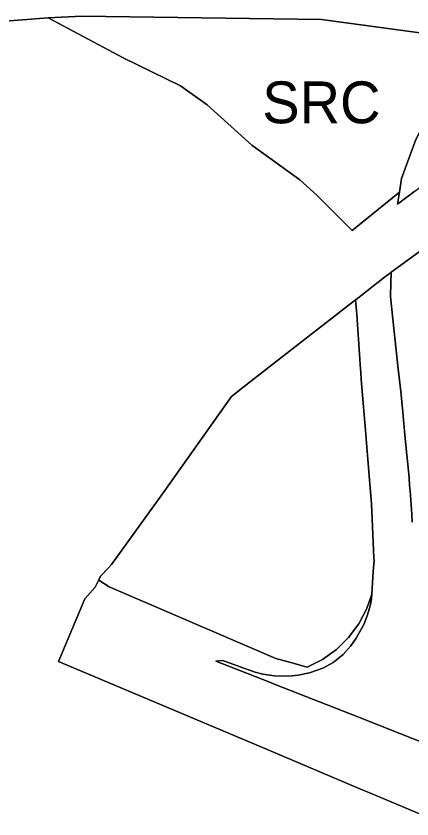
# Model space of a CAD drawing. Extents: x 598968 to 613553, y 4409678 to 4430833.
# Drawn here: x 607149.2 to 607262.7, y 4416952.5 to 4417182.7 of the extents above; entities that cross this region are included whole.
import ezdxf

# ---------------------------------------------------------------- set-up
doc = ezdxf.new("R2010")
doc.units = 0
for name, color, linetype in [('1', 7, 'Continuous'), ('Sòl Rústic Comú', 7, 'Continuous'), ('Sòl Rústic Protegit', 7, 'Continuous')]:
    doc.layers.add(name, color=color, linetype=linetype)

msp = doc.modelspace()

# ---------------------------------------------------------------- linework, layer by layer
at = {"layer": '1'}
for points in [[(607274.8714, 4417122.4396), (607256.7531, 4417109.2766), (607256.6325, 4417106.0969), (607256.4872, 4417102.2661), (607257.1786, 4417095.7896), (607258.7038, 4417081.5028), (607259.4393, 4417074.9859), (607260.0228, 4417069.1469), (607260.0232, 4417069.1429), (607260.6743, 4417062.6279), (607260.9549, 4417059.6622), (607261.7414, 4417051.35), (607261.8422, 4417050.2843), (607261.9968, 4417048.0768), (607262.1401, 4417046.5474), (607262.6256, 4417039.8621), (607262.7304, 4417037.6034)], [(607262.7304, 4417037.6034), (607262.6256, 4417039.8621), (607262.1401, 4417046.5474), (607261.9968, 4417048.0768), (607261.8422, 4417050.2843), (607261.7414, 4417051.35), (607260.9549, 4417059.6622), (607260.6743, 4417062.6279), (607260.0232, 4417069.1429), (607260.0228, 4417069.1469), (607259.4393, 4417074.9859), (607258.7038, 4417081.5028), (607257.1786, 4417095.7896), (607256.4872, 4417102.2661), (607256.6325, 4417106.0969), (607256.7531, 4417109.2766), (607256.7239, 4417109.2554), (607256.4972, 4417109.0907), (607254.4609, 4417107.5042), (607254.369, 4417107.4327), (607246.6902, 4417101.4506), (607246.5298, 4417101.3256), (607246.8279, 4417097.1465), (607247.7412, 4417084.3437), (607247.847, 4417082.7605), (607248.0066, 4417080.3707), (607248.1589, 4417078.4891), (607248.163, 4417078.4378), (607249.5244, 4417061.6174), (607249.5394, 4417061.4308), (607250.1994, 4417053.2371), (607251.042, 4417042.7774), (607251.7855, 4417027.3151), (607251.8196, 4417026.6064), (607251.594, 4417023.4169), (607251.1364, 4417016.9491), (607251.0446, 4417015.6515), (607250.7897, 4417013.8765), (607249.8187, 4417010.6774), (607248.8658, 4417008.2616), (607246.6477, 4417004.3067), (607245.1448, 4417002.0815), (607242.9298, 4416999.6615), (607240.0698, 4416997.3065), (607237.1107, 4416995.6767), (607233.2899, 4416994.3464), (607230.04, 4416993.6864), (607228.3118, 4416993.5449), (607226.74, 4416993.4163), (607223.2148, 4416993.4764), (607219.8901, 4416993.9362), (607217.783, 4416994.55), (607213.4401, 4416996.076), (607208.5102, 4416997.9059), (607207.2773, 4416997.7617), (607206.462, 4416997.6663), (607221.2228, 4416991.9327), (607223.4907, 4416991.0402), (607247.149, 4416981.7304), (607259.2318, 4416976.9757), (607266.9733, 4416973.9293)], [(607266.9733, 4416973.9293), (607259.2318, 4416976.9757), (607247.149, 4416981.7304), (607223.4907, 4416991.0402), (607221.2228, 4416991.9327), (607206.462, 4416997.6663), (607207.2773, 4416997.7617), (607208.5102, 4416997.9059), (607213.4401, 4416996.076), (607217.783, 4416994.55), (607219.8901, 4416993.9362), (607223.2148, 4416993.4764), (607226.74, 4416993.4163), (607228.3118, 4416993.5449), (607230.04, 4416993.6864), (607233.2899, 4416994.3464), (607237.1107, 4416995.6767), (607240.0698, 4416997.3065), (607242.9298, 4416999.6615), (607245.1448, 4417002.0815), (607246.6477, 4417004.3067), (607248.8658, 4417008.2616), (607249.8187, 4417010.6774), (607250.7897, 4417013.8765), (607251.0446, 4417015.6515), (607251.1364, 4417016.9491), (607249.7129, 4417012.7857), (607247.4325, 4417008.4436), (607244.5127, 4417004.5029), (607241.0225, 4417001.0572), (607237.0448, 4416998.1881), (607232.6737, 4416995.9635), (607227.6081, 4416997.3796), (607223.6633, 4416998.4825), (607175.9173, 4417019.0222), (607172.9624, 4417020.9478), (607172.8855, 4417020.998), (607171.8654, 4417018.9129), (607168.9499, 4417015.5498), (607161.364, 4416997.578), (607162.0146, 4416997.3034), (607221.6377, 4416972.1378), (607247.7574, 4416961.1132), (607251.5008, 4416959.5332), (607262.3284, 4416954.9632), (607268.2481, 4416952.4646)]]:
    msp.add_lwpolyline(points, dxfattribs=at)
msp.add_lwpolyline([(607251.1364, 4417016.9491), (607251.594, 4417023.4169), (607251.8196, 4417026.6064), (607251.7855, 4417027.3151), (607251.042, 4417042.7774), (607250.1994, 4417053.2371), (607249.5394, 4417061.4308), (607249.5244, 4417061.6174), (607248.163, 4417078.4378), (607248.1589, 4417078.4891), (607248.0066, 4417080.3707), (607247.847, 4417082.7605), (607247.7412, 4417084.3437), (607246.8279, 4417097.1465), (607246.5298, 4417101.3256), (607216.4384, 4417077.8832), (607210.9686, 4417073.6299), (607191.1592, 4417045.6898), (607176.5596, 4417025.3798), (607175.6604, 4417024.4348), (607173.4098, 4417022.0698), (607172.8855, 4417020.998), (607172.9624, 4417020.9478), (607175.9173, 4417019.0222), (607223.6633, 4416998.4825), (607227.6081, 4416997.3796), (607232.6737, 4416995.9635), (607237.0448, 4416998.1881), (607241.0225, 4417001.0572), (607244.5127, 4417004.5029), (607247.4325, 4417008.4436), (607249.7129, 4417012.7857)], close=True, dxfattribs=at)
at = {"layer": 'Sòl Rústic Comú'}
for points in [[(607259.0954, 4417132.1454), (607259.72, 4417136.06), (607263.82, 4417147.31), (607269.68, 4417158.7), (607274.33, 4417165.87), (607278.04, 4417170.3193), (607281.1345, 4417174.0305), (607269.8557, 4417177.1866), (607236.7443, 4417181.6842), (607168.0575, 4417182.6832), (607158.4327, 4417182.183), (607158.4093, 4417182.1812), (607179.9423, 4417170.697), (607196.3173, 4417162.697), (607204.0049, 4417157.197), (607216.8175, 4417145.697), (607230.5677, 4417135.697), (607235.5051, 4417131.197), (607245.5677, 4417121.197)], [(607310.6373, 4417162.4695), (607300.1935, 4417168.6971), (607281.1345, 4417174.0305), (607278.04, 4417170.3193), (607274.33, 4417165.87), (607269.68, 4417158.7), (607263.82, 4417147.31), (607259.72, 4417136.06), (607259.0954, 4417132.1454), (607258.56, 4417128.79), (607263.53, 4417132.5088), (607273.1484, 4417139.7058), (607296.5493, 4417153.8893)]]:
    msp.add_lwpolyline(points, close=True, dxfattribs=at)
at = {"layer": 'Sòl Rústic Protegit'}
for points in [[(607106.8165, 4417178.197), (607158.3795, 4417182.197), (607158.4093, 4417182.1812), (607158.4327, 4417182.183), (607168.0575, 4417182.6832), (607236.7443, 4417181.6842), (607269.8557, 4417177.1866)], [(607263.53, 4417132.5088), (607258.56, 4417128.79), (607259.0954, 4417132.1454), (607245.5677, 4417121.197), (607235.5051, 4417131.197), (607230.5677, 4417135.697), (607216.8175, 4417145.697), (607204.0049, 4417157.197), (607196.3173, 4417162.697), (607179.9423, 4417170.697), (607158.4093, 4417182.1812), (607158.3795, 4417182.197), (607106.8165, 4417178.197)], [(607268.2481, 4416952.4646), (607262.3284, 4416954.9632), (607251.5008, 4416959.5332), (607247.7574, 4416961.1132), (607221.6377, 4416972.1378), (607162.0146, 4416997.3034), (607161.364, 4416997.578), (607168.9499, 4417015.5498), (607171.8654, 4417018.9129), (607172.8855, 4417020.998), (607173.4098, 4417022.0698), (607175.6604, 4417024.4348), (607176.5596, 4417025.3798), (607191.1592, 4417045.6898), (607210.9686, 4417073.6299), (607216.4384, 4417077.8832), (607246.5298, 4417101.3256), (607246.6902, 4417101.4506), (607254.369, 4417107.4327), (607254.4609, 4417107.5042), (607256.4972, 4417109.0907), (607256.7239, 4417109.2554), (607256.7531, 4417109.2766), (607274.8714, 4417122.4396)]]:
    msp.add_lwpolyline(points, dxfattribs=at)

# ---------------------------------------------------------------- texts
at = {"layer": 'Sòl Rústic Comú'}
msp.add_text('SRC', height=12, dxfattribs=at).set_placement((607219.7719, 4417151.9401))

doc.saveas('drawing.dxf')
